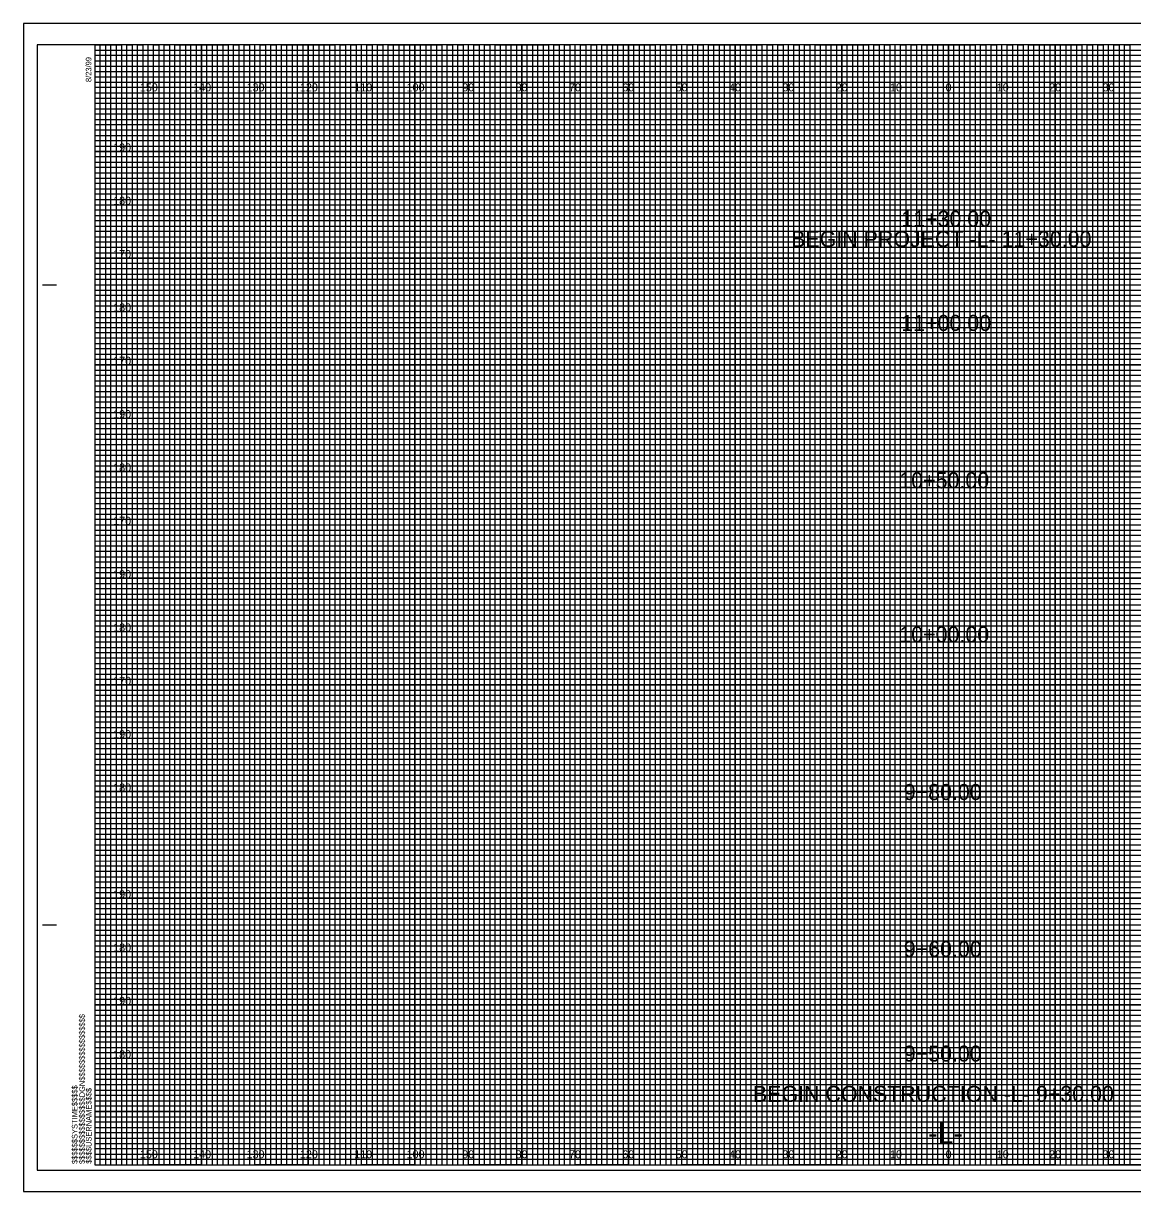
# Model space of a CAD drawing. Extents: x -13 to 323, y -5 to 214.
# Drawn here: x -13.4 to 194.5, y -5 to 214 of the extents above; entities that cross this region are included whole.
import ezdxf

# ---------------------------------------------------------------- set-up
doc = ezdxf.new("R2010")
doc.units = 0
for name, color, linetype in [('Prop XS Alignment Label', 7, 'Continuous'), ('Prop XS Elevation Labels', 7, 'Continuous'), ('Prop XS Offset Labels', 7, 'Continuous'), ('Prop XS Station Labels', 7, 'Continuous'), ('Sheet Cross Section CELL', 7, 'Continuous'), ('Sheet Cross Section Grid Major CELL', 7, 'Continuous'), ('Sheet Cross Section Grid Middle CELL', 7, 'Continuous'), ('Sheet Cross Section Grid Minor 1 CELL', 7, 'Continuous'), ('Sheet Cross Section Grid Minor 2 CELL', 7, 'Continuous'), ('Sheet Cutting Line CELL', 7, 'Continuous'), ('Sheet DOT Grid CELL', 7, 'Continuous'), ('Sheet Plot Border Inside CELL', 7, 'Continuous'), ('Sheet Plot Border Outside CELL', 7, 'Continuous')]:
    doc.layers.add(name, color=color, linetype=linetype)

msp = doc.modelspace()

# ---------------------------------------------------------------- linework, layer by layer
at = {"layer": 'Sheet Cross Section CELL'}
for p, q in [((-9.8, 165), (-7.3, 165)), ((-9.7, 165), (-7.2, 165)), ((-9.8, 45), (-7.3, 45)), ((-9.7, 45), (-7.2, 45)), ((0, 0), (0, 0)), ((0, 0), (0, 0)), ((0, 0), (0, 0)), ((0, 0), (0, 0)), ((0, 0), (0, 0)), ((0, 0), (0, 0)), ((0, 0), (0, 0))]:
    msp.add_line(p, q, dxfattribs=at)
msp.add_lwpolyline([(320, 210), (0, 210), (0, 0), (320, 0)], close=True, dxfattribs=at)
at = {"layer": 'Sheet Cross Section Grid Major CELL'}
for p, q in [((10, 210), (0, 210)), ((10, 0), (10, 210)), ((30, 210), (20, 210)), ((20, 210), (20, 0)), ((30, 0), (30, 210)), ((50, 210), (40, 210)), ((40, 210), (40, 0)), ((50, 0), (50, 210)), ((70, 210), (60, 210)), ((60, 210), (60, 0)), ((70, 0), (70, 210)), ((90, 210), (80, 210)), ((80, 210), (80, 0)), ((90, 0), (90, 210)), ((110, 210), (100, 210)), ((100, 210), (100, 0)), ((110, 0), (110, 210)), ((130, 210), (120, 210)), ((120, 210), (120, 0)), ((130, 0), (130, 210)), ((150, 210), (140, 210)), ((140, 210), (140, 0)), ((150, 0), (150, 210)), ((170, 210), (160, 210)), ((160, 210), (160, 0)), ((170, 0), (170, 210)), ((190, 210), (180, 210)), ((180, 210), (180, 0)), ((190, 0), (190, 210)), ((20, 0), (10, 0)), ((40, 0), (30, 0)), ((60, 0), (50, 0)), ((80, 0), (70, 0)), ((100, 0), (90, 0)), ((120, 0), (110, 0)), ((140, 0), (130, 0)), ((160, 0), (150, 0)), ((180, 0), (170, 0)), ((200, 0), (190, 0))]:
    msp.add_line(p, q, dxfattribs=at)
for points in [[(0, 200), (320, 200), (320, 190), (0, 190)], [(0, 180), (320, 180), (320, 170), (0, 170)], [(0, 160), (320, 160), (320, 150), (0, 150)], [(0, 140), (320, 140), (320, 130), (0, 130)], [(0, 120), (320, 120), (320, 110), (0, 110)], [(0, 100), (320, 100), (320, 90), (0, 90)], [(0, 80), (320, 80), (320, 70), (0, 70)], [(0, 60), (320, 60), (320, 50), (0, 50)], [(0, 40), (320, 40), (320, 30), (0, 30)], [(0, 20), (320, 20), (320, 10), (0, 10)]]:
    msp.add_lwpolyline(points, dxfattribs=at)
at = {"layer": 'Sheet Cross Section Grid Middle CELL'}
for points in [[(0, 210), (5, 210), (5, 0), (15, 0), (15, 210), (25, 210), (25, 0), (35, 0), (35, 210), (45, 210), (45, 0), (55, 0), (55, 210), (65, 210), (65, 0), (75, 0), (75, 210), (85, 210), (85, 0), (95, 0), (95, 210), (105, 210), (105, 0), (115, 0), (115, 210), (125, 210), (125, 0), (135, 0), (135, 210), (145, 210), (145, 0), (155, 0), (155, 210), (165, 210), (165, 0), (175, 0), (175, 210), (185, 210), (185, 0), (195, 0)], [(0, 205), (275, 205)], [(0, 185), (320, 185), (320, 195), (0, 195)], [(0, 165), (320, 165), (320, 175), (0, 175)], [(0, 145), (320, 145), (320, 155), (0, 155)], [(0, 125), (320, 125), (320, 135), (0, 135)], [(0, 105), (320, 105), (320, 115), (0, 115)], [(0, 85), (320, 85), (320, 95), (0, 95)], [(0, 65), (320, 65), (320, 75), (0, 75)], [(0, 45), (320, 45), (320, 55), (0, 55)], [(0, 25), (320, 25), (320, 35), (0, 35)], [(0, 5), (320, 5), (320, 15), (0, 15)]]:
    msp.add_lwpolyline(points, dxfattribs=at)
at = {"layer": 'Sheet Cross Section Grid Minor 1 CELL'}
for p, q in [((0, 209), (260, 209)), ((260, 207.98), (0, 207.98)), ((0, 207.98), (0, 207)), ((0, 207), (260, 207)), ((260, 205.89), (0, 205.89)), ((0, 205.89), (0, 204)), ((0, 204), (320, 204))]:
    msp.add_line(p, q, dxfattribs=at)
for points in [[(0, 203), (270, 203), (320, 203), (320, 202), (0, 202)], [(0, 201), (320, 201), (320, 199), (0, 199)], [(0, 198), (320, 198), (320, 197), (0, 196.98)], [(0, 196), (320, 196), (320, 194), (0, 194)], [(0, 193), (320, 193), (320, 192), (0, 192)], [(0, 191), (320, 191), (320, 189), (0, 189)], [(0, 188), (320, 188), (320, 187), (0, 187)], [(0, 186), (320, 186), (320, 184), (0, 184)], [(0, 183), (320, 183), (320, 182), (0, 182)], [(0, 181), (320, 181), (320, 179), (0, 179)], [(0, 178), (320, 178), (320, 177), (0, 177)], [(0, 176), (320, 176), (320, 173.95), (320, 173), (320, 172), (0, 172)], [(0, 174), (320, 174), (320, 173), (0, 173)], [(0, 171), (320, 171), (320, 169), (0, 169.03)], [(0, 169.03), (320, 169), (320, 168), (0, 168)], [(0, 167), (320, 167), (320, 166), (0, 166)], [(0, 164), (320, 164), (320, 163), (0, 163)], [(0, 162), (320, 162), (320, 161), (0, 161)], [(-0.07, 158.89), (320, 158.89), (320, 157.88), (-0.07, 157.88)], [(0, 157), (320, 157), (320, 156), (0, 156)], [(0, 154), (320, 154), (320, 153), (0, 153)], [(0, 152), (320, 152), (320, 151), (0, 151)], [(0, 149), (320, 149), (320, 148), (0, 148)], [(0, 147), (320, 147), (320, 146), (0, 146)], [(0, 144), (320, 144), (320, 143), (0, 143)], [(0, 142), (320, 142), (320, 141), (0, 141)], [(0, 139), (320, 139), (319.99, 137.98), (0, 138)], [(0, 137), (320, 137), (320, 136), (0, 136)], [(0, 134), (320, 134), (320, 133), (0, 133)], [(0, 132), (320, 132), (320, 131), (0, 131)], [(0, 129), (320, 129), (320, 128), (0, 128)], [(0, 127), (320, 127), (320, 126), (0, 126)], [(0, 124), (320, 124), (320, 123), (0, 123)], [(0, 122), (320, 122), (320, 121), (0, 121)], [(0, 119), (320, 119), (320, 118), (0, 118)], [(0, 116.99), (320.07, 116.91), (320, 116), (0, 116)], [(0, 114), (320, 114), (320, 113), (0, 113)], [(0, 112), (320, 112), (320, 111), (0, 111)], [(0, 109), (320, 109), (320, 108), (0, 108)], [(0, 107), (320, 107), (320, 106), (0, 106)], [(0, 104), (320, 104), (320, 103), (0, 103)], [(0, 102), (320, 102), (320, 101), (0, 101)], [(0, 99), (320, 99), (320, 98), (0, 98)], [(0, 97), (320, 97), (320, 96), (0, 96)], [(0, 94), (320, 94), (320, 93), (0, 93)], [(0, 92), (320, 92), (320, 91), (0, 91)], [(0, 89), (320, 89), (320, 88), (0, 88)], [(0, 87), (320, 87), (320, 86), (0, 86)], [(0, 84), (320, 84), (320, 83), (0, 83)], [(0, 82), (320, 82), (320, 81), (0, 81)], [(0, 79), (320, 79), (319.99, 77.98), (0, 78)], [(0, 77), (320, 77), (320, 76), (0, 76)], [(0, 74), (320, 74), (320, 73), (0, 73)], [(0, 72), (320, 72), (320, 71), (0, 71)], [(0, 69), (320, 69), (320, 68), (0, 68)], [(0, 67), (320, 67), (320, 66), (0, 66)], [(0, 64), (320, 64), (320, 63), (0, 63)], [(0, 62), (320, 62), (320, 61), (0, 61)], [(0, 59), (320, 59), (320, 58), (0, 58)], [(0, 56.99), (320.07, 56.91), (320, 56), (0, 56)], [(0, 54), (320, 54), (320, 53), (0, 53)], [(0, 52), (320, 52), (320, 51), (0, 51)], [(0, 49), (320, 49), (320, 48), (0, 48)], [(0, 47), (320, 47), (320, 46), (0, 46)], [(0, 44), (320, 44), (320, 43), (0, 43)], [(0, 42), (320, 42), (320, 41), (0, 41)], [(0, 39), (320, 39), (320, 38), (0, 38)], [(0, 37), (320, 37), (320, 36), (0, 36)], [(0, 34), (320, 34), (320, 33), (0, 33)], [(0, 32), (320, 32), (320, 31), (0, 31)], [(0, 29), (320, 29), (320, 28), (0, 28)], [(0, 27), (320, 27), (320, 26), (0, 26)], [(0, 24), (320, 24), (320, 23), (0, 23)], [(0, 22), (320, 22), (320, 21), (0, 21)], [(0, 19), (320, 19), (320, 18), (0, 18)], [(0, 17), (320, 17), (320, 16), (0, 16)], [(0, 14), (320, 14), (320, 13), (0, 13)], [(0, 12), (320, 12), (320, 11), (0, 11)], [(0, 9), (320, 9), (320, 8), (0, 8)], [(0, 7), (320, 7), (320, 6), (0, 6)], [(0, 4), (320, 4), (320, 3), (0, 3)], [(0, 2), (320, 2), (320, 1), (0, 1)]]:
    msp.add_lwpolyline(points, dxfattribs=at)
at = {"layer": 'Sheet Cross Section Grid Minor 2 CELL'}
for points in [[(0, 0), (1, 0), (1, 210), (2, 210), (2, 0)], [(2, 0), (3, 0), (3, 210), (4, 210), (4, 0)], [(5, 0), (6, 0), (6, 210), (7, 210), (7, 0)], [(7, 0), (8, 0), (8, 210), (9, 210), (9, 0)], [(10, 0), (11, 0), (11, 210), (12, 210), (12, 0)], [(12, 0), (13, 0), (13, 210), (14, 210), (14, 0)], [(15, 0), (16, 0), (16, 210), (17, 210), (17, 0)], [(17, 0), (18, 0), (18, 210), (19, 210), (19, 0)], [(20, 0), (21, 0), (21, 210), (22, 210), (22, 0)], [(22, 0), (23, 0), (23, 210), (24, 210), (24, 0)], [(25, 0), (26, 0), (26, 210), (27, 210), (27, 0)], [(27, 0), (28, 0), (28, 210), (29, 210), (29, 0)], [(30, 0), (31, 0), (31, 210), (32, 210), (32, 0)], [(32, 0), (33, 0), (33, 210), (34, 210), (34, 0)], [(35, 0), (36, 0), (36, 210), (37, 210), (37, 0)], [(37, 0), (38, 0), (38, 210), (39, 210), (39, 0)], [(40, 0), (41, 0), (41, 210), (42, 210), (42, 0)], [(42, 0), (43, 0), (43, 210), (44, 210), (44, 0)], [(45, 0), (46, 0), (46, 210), (47, 210), (47, 0)], [(47, 0), (48, 0), (48, 210), (49, 210), (49, 0)], [(50, 0), (51, 0), (51, 210), (52, 210), (52, 0)], [(52, 0), (53, 0), (53, 210), (54, 210), (54, 0)], [(55, 0), (56, 0), (56, 210), (57, 210), (57, 0)], [(57, 0), (58, 0), (58, 210), (59, 210), (59, 0)], [(60, 0), (61, 0), (61, 210), (62, 210), (62, 0)], [(62, 0), (63, 0), (63, 210), (64, 210), (64, 0)], [(65, 0), (66, 0), (66, 210), (67, 210), (67, 0)], [(67, 0), (68, 0), (68, 210), (69, 210), (69, 0)], [(70, 0), (71, 0), (71, 210), (72, 210), (72, 0)], [(72, 0), (73, 0), (73, 210), (74, 210), (74, 0)], [(75, 0), (76, 0), (76, 210), (77, 210), (77, 0)], [(77, 0), (78, 0), (78, 210), (79, 210), (79, 0)], [(80, 0), (81, 0), (81, 210), (82, 210), (82, 0)], [(82, 0), (83, 0), (83, 210), (84, 210), (84, 0)], [(85, 0), (86, 0), (86, 210), (87, 210), (87, 0)], [(87, 0), (88, 0), (88, 210), (89, 210), (89, 0)], [(90, 0), (91, 0), (91, 210), (92, 210), (92, 0)], [(92, 0), (93, 0), (93, 210), (94, 210), (94, 0)], [(95, 0), (96, 0), (96, 210), (97, 210), (97, 0)], [(97, 0), (98, 0), (98, 210), (99, 210), (99, 0)], [(100, 0), (101, 0), (101, 210), (102, 210), (102, 0)], [(102, 0), (103, 0), (103, 210), (104, 210), (104, 0)], [(105, 0), (106, 0), (106, 210), (107, 210), (107, 0)], [(107, 0), (108, 0), (108, 210), (109, 210), (109, 0)], [(110, 0), (111, 0), (111, 210), (112, 210), (112, 0)], [(112, 0), (113, 0), (113, 210), (114, 210), (114, 0)], [(115, 0), (116, 0), (116, 210), (117, 210), (117, 0)], [(117, 0), (118, 0), (118, 210), (119, 210), (119, 0)], [(120, 0), (121, 0), (121, 210), (122, 210), (122, 0)], [(122, 0), (123, 0), (123, 210), (124, 210), (124, 0)], [(125, 0), (126, 0), (126, 210), (127, 210), (127, 0)], [(127, 0), (128, 0), (128, 210), (129, 210), (129, 0)], [(130, 0), (131, 0), (131, 210), (132, 210), (132, 0)], [(132, 0), (133, 0), (133, 210), (134, 210), (134, 0)], [(135, 0), (136, 0), (136, 210), (137, 210), (137, 0)], [(137, 0), (138, 0), (138, 210), (139, 210), (139, 0)], [(140, 0), (141, 0), (141, 210), (142, 210), (142, 0)], [(142, 0), (143, 0), (143, 210), (144, 210), (144, 0)], [(145, 0), (146, 0), (146, 210), (147, 210), (147, 0)], [(147, 0), (148, 0), (148, 210), (149, 210), (149, 0)], [(150, 0), (151, 0), (151, 210), (152, 210), (152, 0)], [(152, 0), (153, 0), (153, 210), (154, 210), (154, 0)], [(155, 0), (156, 0), (156, 210), (157, 210), (157, 0)], [(157, 0), (158, 0), (158, 210), (159, 210), (159, 0)], [(160, 0), (161, 0), (161, 210), (162, 210), (162, 0)], [(162, 0), (163, 0), (163, 210), (164, 210), (164, 0)], [(165, 0), (166, 0), (166, 210), (167, 210), (167, 0)], [(167, 0), (168, 0), (168, 210), (169, 210), (169, 0)], [(170, 0), (171, 0), (171, 210), (172, 210), (172, 0)], [(172, 0), (173, 0), (173, 210), (174, 210), (174, 0)], [(175, 0), (176, 0), (176, 210), (177, 210), (177, 0)], [(177, 0), (178, 0), (178, 210), (179, 210), (179, 0)], [(180, 0), (181, 0), (181, 210), (182, 210), (182, 0)], [(182, 0), (183, 0), (183, 210), (184, 210), (184, 0)], [(185, 0), (186, 0), (186, 210), (187, 210), (187, 0)], [(187, 0), (188, 0), (188, 210), (189, 210), (189, 0)], [(190, 0), (191, 0), (191, 210), (192, 210), (192, 0)], [(192, 0), (193, 0), (193, 210), (194, 210), (194, 0)]]:
    msp.add_lwpolyline(points, dxfattribs=at)
at = {"layer": 'Sheet Cutting Line CELL'}
for p, q in [((323.3, 214), (-13.4, 214)), ((-13.4, 214), (-13.4, -5)), ((-13.4, -5), (323.3, -5))]:
    msp.add_line(p, q, dxfattribs=at)
at = {"layer": 'Sheet DOT Grid CELL'}
for p, q in [((10, 0), (10, 210)), ((20, 0), (20, 210)), ((30, 0), (30, 210)), ((40, 0), (40, 210)), ((50, 0), (50, 210)), ((60, 0), (60, 210)), ((70, 0), (70, 210)), ((80, 0), (80, 210)), ((90, 0), (90, 210)), ((100, 0), (100, 210)), ((110, 0), (110, 210)), ((120, 0), (120, 210)), ((130, 0), (130, 210)), ((140, 0), (140, 210)), ((150, 0), (150, 210)), ((160, 0), (160, 210)), ((170, 0), (170, 210)), ((180, 0), (180, 210)), ((190, 0), (190, 210)), ((0, 200), (320, 200)), ((0, 190), (320, 190)), ((0, 180), (320, 180)), ((0, 170), (320, 170)), ((0, 160), (320, 160)), ((0, 150), (320, 150)), ((0, 140), (320, 140)), ((0, 130), (320, 130)), ((0, 120), (320, 120)), ((0, 110), (320, 110)), ((0, 100), (320, 100)), ((0, 90), (320, 90)), ((0, 80), (320, 80)), ((0, 70), (320, 70)), ((0, 60), (320, 60)), ((0, 50), (320, 50)), ((0, 40), (320, 40)), ((0, 30), (320, 30)), ((0, 20), (320, 20)), ((0, 10), (320, 10))]:
    msp.add_line(p, q, dxfattribs=at)
at = {"layer": 'Sheet Plot Border Inside CELL'}
msp.add_lwpolyline([(-10.8, -1), (322.4, -1), (322.4, 210), (-10.8, 210)], close=True, dxfattribs=at)
at = {"layer": 'Sheet Plot Border Outside CELL'}
msp.add_lwpolyline([(-13.4, -5), (323.3, -5), (323.3, 214), (-13.4, 214)], close=True, dxfattribs=at)

# ---------------------------------------------------------------- texts
at = {"layer": 'Prop XS Alignment Label'}
msp.add_text('-L-', height=4, dxfattribs=at).set_placement((156.15, 4))
at = {"layer": 'Prop XS Elevation Labels'}
for s, p in [('190', (3.44, 190)), ('180', (3.44, 180)), ('170', (3.44, 170)), ('180', (3.44, 160)), ('170', (3.44, 150)), ('190', (3.44, 140)), ('180', (3.44, 130)), ('170', (3.44, 120)), ('190', (3.44, 110)), ('180', (3.44, 100)), ('170', (3.44, 90)), ('190', (3.44, 80)), ('180', (3.44, 70)), ('190', (3.44, 50)), ('180', (3.44, 40)), ('190', (3.44, 30)), ('180', (3.44, 20))]:
    msp.add_text(s, height=1.5, dxfattribs=at).set_placement(p)
at = {"layer": 'Prop XS Offset Labels'}
for s, p in [('150', (8.44, 201.25)), ('140', (18.44, 201.25)), ('130', (28.44, 201.25)), ('120', (38.44, 201.25)), ('110', (48.62, 201.25)), ('100', (58.44, 201.25)), ('90', (68.86, 201.25)), ('80', (78.86, 201.25)), ('70', (88.86, 201.25)), ('60', (98.86, 201.25)), ('50', (108.86, 201.25)), ('40', (118.86, 201.25)), ('30', (128.86, 201.25)), ('20', (138.86, 201.25)), ('10', (149.04, 201.25)), ('0', (159.45, 201.25)), ('0', (159.45, 201.25)), ('10', (169.04, 201.25)), ('20', (178.86, 201.25)), ('30', (188.86, 201.25)), ('150', (8.44, 1.25)), ('140', (18.44, 1.25)), ('130', (28.44, 1.25)), ('120', (38.44, 1.25)), ('110', (48.62, 1.25)), ('100', (58.44, 1.25)), ('90', (68.86, 1.25)), ('80', (78.86, 1.25)), ('70', (88.86, 1.25)), ('60', (98.86, 1.25)), ('50', (108.86, 1.25)), ('40', (118.86, 1.25)), ('30', (128.86, 1.25)), ('20', (138.86, 1.25)), ('10', (149.04, 1.25)), ('0', (159.45, 1.25)), ('0', (159.45, 1.25)), ('10', (169.04, 1.25)), ('20', (178.86, 1.25)), ('30', (188.86, 1.25))]:
    msp.add_text(s, height=1.5, dxfattribs=at).set_placement(p)
at = {"layer": 'Prop XS Station Labels'}
for s, p in [('11+30.00', (151.13, 175.87)), ('BEGIN PROJECT -L- 11+30.00', (130.49, 172.08)), ('11+00.00', (151.13, 156.34)), ('10+50.00', (150.77, 126.84)), ('10+00.00', (150.77, 97.96)), ('9+80.00', (151.6, 68.41)), ('9+60.00', (151.6, 38.98)), ('9+50.00', (151.6, 19.38)), ('BEGIN CONSTRUCTION -L- 9+30.00', (123.33, 11.83))]:
    msp.add_text(s, height=3, dxfattribs=at).set_placement(p)
at = {"layer": 'Sheet Cross Section CELL'}
for s, p in [('8/23/99', (-0.65, 203)), ('$$$$$$$$$$$$$$$$DGN$$$$$$$$$$$$$$$$', (-1.88, 0.18)), ('$$$$$$SYSTIME$$$$$', (-3.26, 0.18)), ('$$$$USERNAME$$$$', (-0.62, 0.23))]:
    msp.add_text(s, height=1.05, rotation=90, dxfattribs=at).set_placement(p)

doc.saveas('drawing.dxf')
